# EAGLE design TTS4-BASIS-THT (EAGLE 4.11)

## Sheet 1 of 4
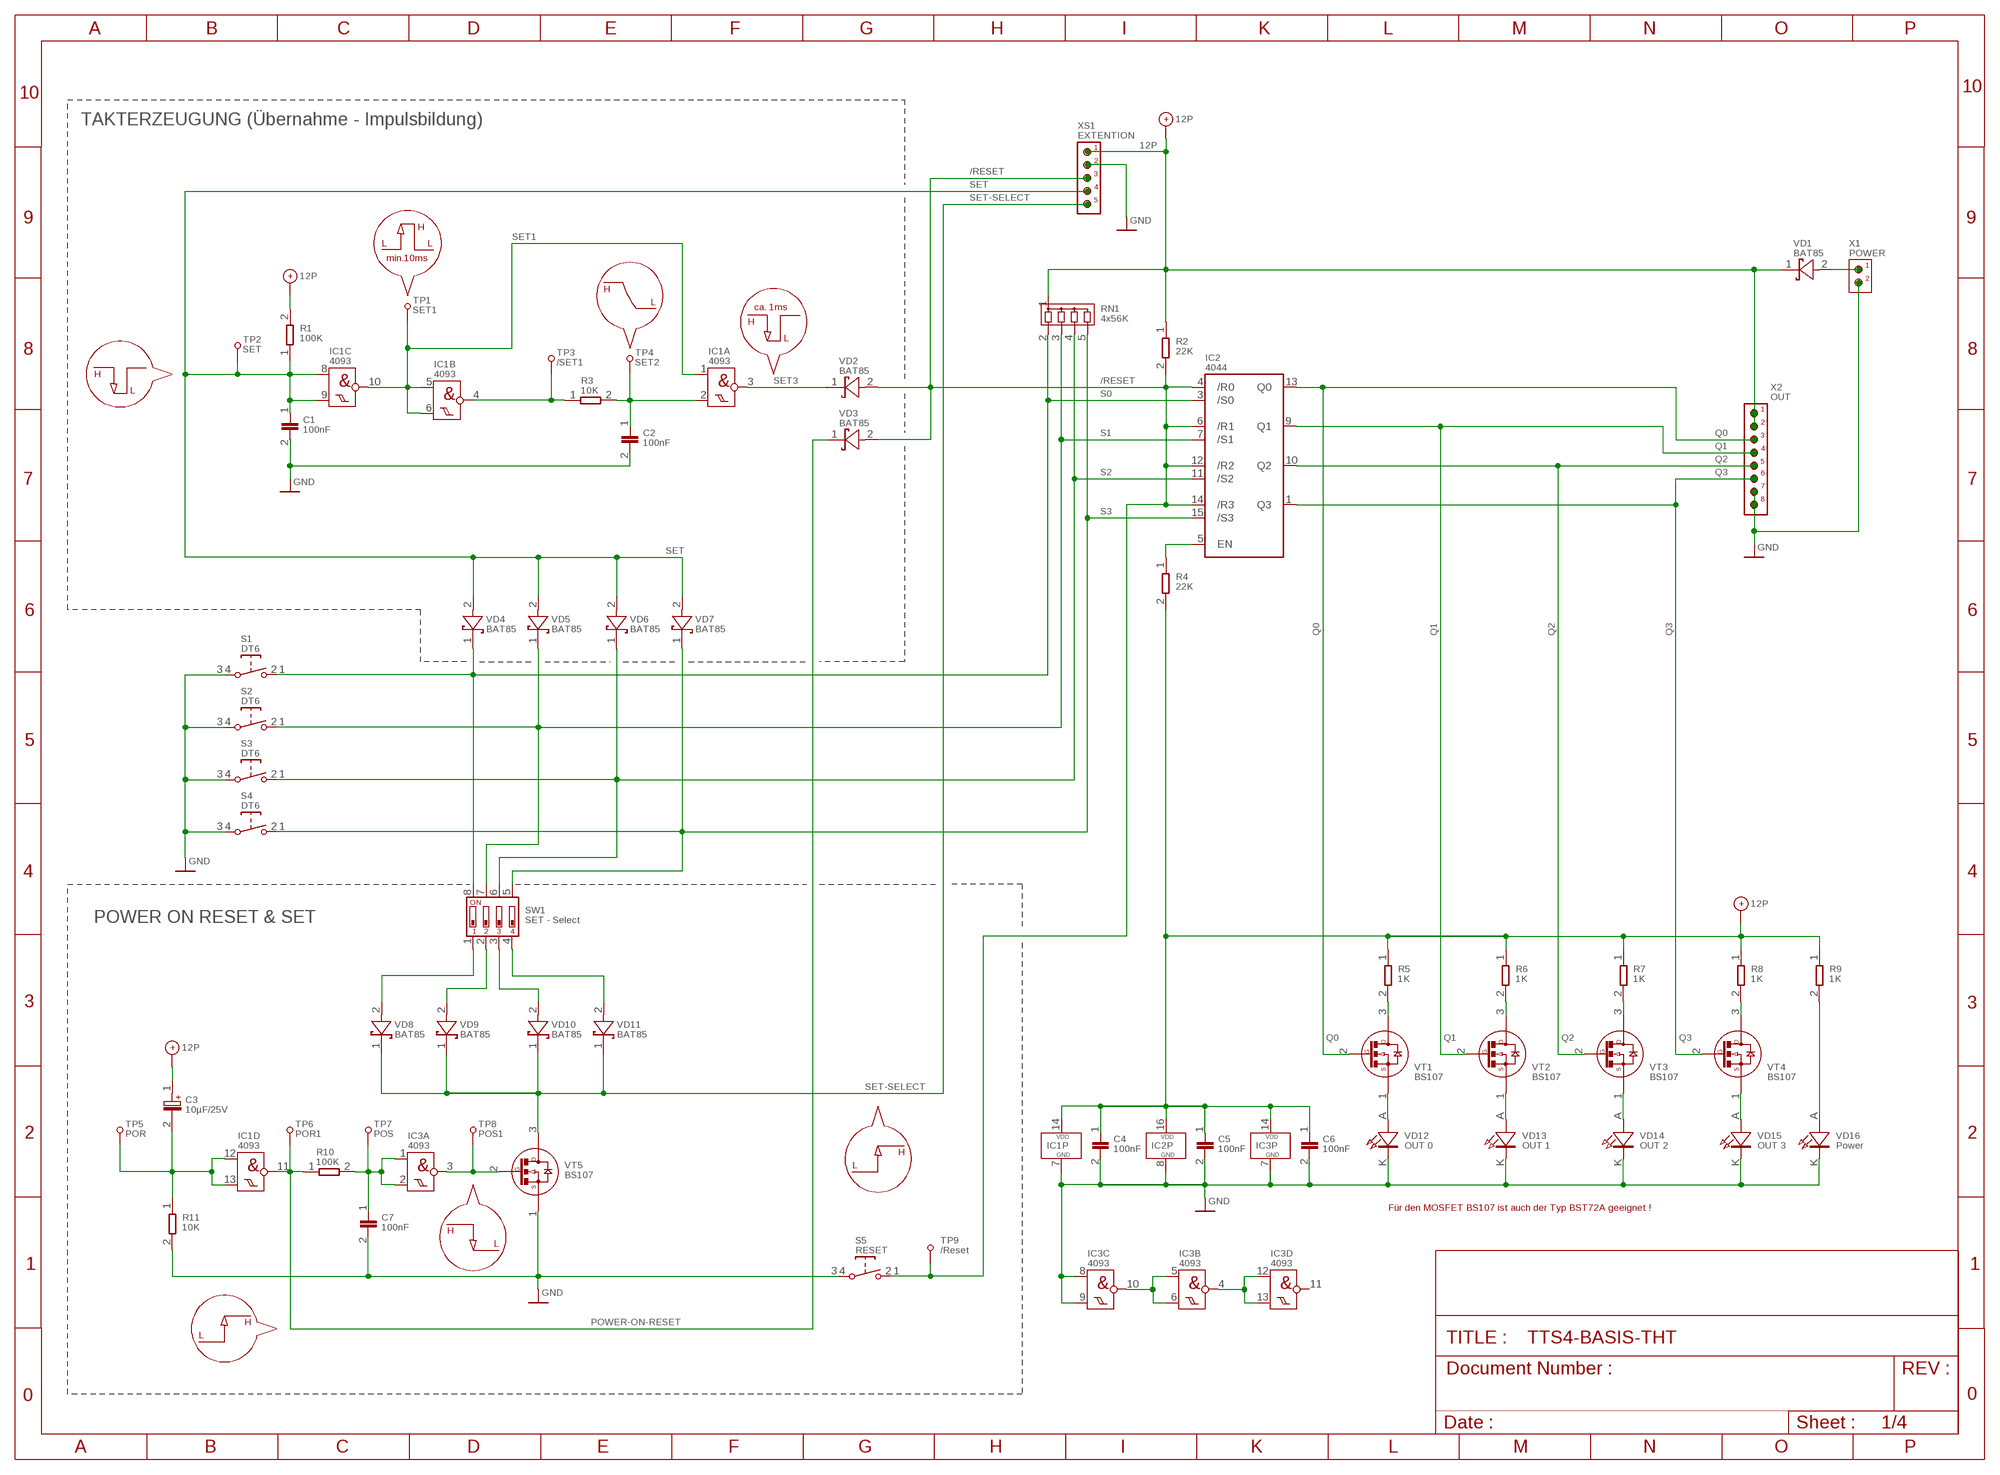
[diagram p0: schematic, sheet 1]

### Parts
C1  100nF  C-5  [C5]
C2  100nF  C-5  [C5]
C3  10µF/25V  ELKO_2,5-5  [EL2,5-5]
C4  100nF  C-5  [C5]
C5  100nF  C-5  [C5]
C6  100nF  C-5  [C5]
C7  100nF  C-5  [C5]
IC1  4093  4093_LP  [DIL14LP]
IC2  4044  4044_LP  [DIL16LP]
IC3  4093  4093_LP  [DIL14LP]
R1  100K  R0207-12,5  [R0207-12,5]
R2  22K  R0207-12,5  [R0207-12,5]
R3  10K  R0207-12,5  [R0207-12,5]
R4  22K  R0207-12,5  [R0207-12,5]
R5  1K  R0207-12,5  [R0207-12,5]
R6  1K  R0207-12,5  [R0207-12,5]
R7  1K  R0207-12,5  [R0207-12,5]
R8  1K  R0207-12,5  [R0207-12,5]
R9  1K  R0207-12,5  [R0207-12,5]
R10  100K  R0207-12,5  [R0207-12,5]
R11  10K  R0207-12,5  [R0207-12,5]
RN1  4x56K  RN4  [RN4]
S1  DT6  DT6-H  [DT6-HOLE]
S2  DT6  DT6-H  [DT6-HOLE]
S3  DT6  DT6-H  [DT6-HOLE]
S4  DT6  DT6-H  [DT6-HOLE]
S5  RESET  DT6-H  [DT6-HOLE]
SW1  SET - Select  SW_DIP-4EPG  [EDG-04]
TP1  SET1  TP1.5  [TP1.5MM]
TP2  SET  TP1.5  [TP1.5MM]
TP3  /SET1  TP1.5  [TP1.5MM]
TP4  SET2  TP1.5  [TP1.5MM]
TP5  POR  TP1.5  [TP1.5MM]
TP6  POR1  TP1.5  [TP1.5MM]
TP7  POS  TP1.5  [TP1.5MM]
TP8  POS1  TP1.5  [TP1.5MM]
TP9  /Reset  TP1.5  [TP1.5MM]
VD1  BAT85  BAT85-DO  [DO35-10]
VD2  BAT85  BAT85-DO  [DO35-10]
VD3  BAT85  BAT85-DO  [DO35-10]
VD4  BAT85  BAT85-DO  [DO35-10]
VD5  BAT85  BAT85-DO  [DO35-10]
VD6  BAT85  BAT85-DO  [DO35-10]
VD7  BAT85  BAT85-DO  [DO35-10]
VD8  BAT85  BAT85-DO  [DO35-10]
VD9  BAT85  BAT85-DO  [DO35-10]
VD10  BAT85  BAT85-DO  [DO35-10]
VD11  BAT85  BAT85-DO  [DO35-10]
VD12  OUT 0  LED3MM  [LED-3MM]
VD13  OUT 1  LED3MM  [LED-3MM]
VD14  OUT 2  LED3MM  [LED-3MM]
VD15  OUT 3  LED3MM  [LED-3MM]
VD16  Power  LED3MM  [LED-3MM]
VT1  BS107  BS107-92A  [TO92A0]
VT2  BS107  BS107-92A  [TO92A0]
VT3  BS107  BS107-92A  [TO92A0]
VT4  BS107  BS107-92A  [TO92A0]
VT5  BS107  BS107-92A  [TO92A0]
X1  POWER  PAD2_PF  [1X2]
X2  OUT  PAD8_PF  [1X8]
XS1  EXTENTION  PF1X5  [1X5]

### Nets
12P: C3.1 C4.1 C5.1 C6.1 IC1.14(P:VDD) IC2.16(VDD) IC3.14(P:VDD) R1.2 R2.1 R4.2 R5.1 R6.1 R7.1 R8.1 R9.1 RN1.1 VD1.1(K) X2.1 X2.2 XS1.1
12PIN: VD1.2(A) X1.1
/RESET: IC2.4(/R0) IC2.6(/R1) IC2.12(/R2) IC2.14(/R3) R2.2 S5.1(S) S5.2(S) TP9.1 VD2.2(A) VD3.2(A) XS1.3
/SET1: IC1.4(B:O) R3.1 TP3.1
GND: C1.2 C2.2 C4.2 C5.2 C6.2 C7.2 IC1.7(P:GND) IC2.8(GND) IC3.7(P:GND) IC3.8(C:I0) IC3.9(C:I1) R11.2 S1.3(P) S1.4(P) S2.3(P) S2.4(P) S3.3(P) S3.4(P) S4.3(P) S4.4(P) S5.3(P) S5.4(P) VD12.K VD13.K VD14.K VD15.K VD16.K VT5.1(S) X1.2 X2.7 X2.8 XS1.2
N$5: VD12.A VT1.1(S)
N$6: VD13.A VT2.1(S)
N$7: VD14.A VT3.1(S)
N$8: VD15.A VT4.1(S)
N$9: IC2.5(EN) R4.1
N$11: R5.2 VT1.3(D)
N$12: R6.2 VT2.3(D)
N$13: R7.2 VT3.3(D)
N$14: R8.2 VT4.3(D)
N$19: R9.2 VD16.A
N$20: IC3.5(B:I0) IC3.6(B:I1) IC3.10(C:O)
N$21: IC3.4(B:O) IC3.12(D:I0) IC3.13(D:I1)
POR: C3.2 IC1.12(D:I0) IC1.13(D:I1) R11.1 TP5.1
POS: C7.1 IC3.1(A:I0) IC3.2(A:I1) R10.2 TP7.1
POS1: IC3.3(A:O) TP8.1 VT5.2(G)
POWER-ON-RESET: IC1.11(D:O) R10.1 TP6.1 VD3.1(K)
Q0: IC2.13(Q0) VT1.2(G) X2.3
Q1: IC2.9(Q1) VT2.2(G) X2.4
Q2: IC2.10(Q2) VT3.2(G) X2.5
Q3: IC2.1(Q3) VT4.2(G) X2.6
S0: IC2.3(/S0) RN1.2 S1.1(S) S1.2(S) SW1.8 VD4.1(K)
S1: IC2.7(/S1) RN1.3 S2.1(S) S2.2(S) SW1.7 VD5.1(K)
S2: IC2.11(/S2) RN1.4 S3.1(S) S3.2(S) SW1.6 VD6.1(K)
S3: IC2.15(/S3) RN1.5 S4.1(S) S4.2(S) SW1.5 VD7.1(K)
SET: C1.1 IC1.8(C:I0) IC1.9(C:I1) R1.1 TP2.1 VD4.2(A) VD5.2(A) VD6.2(A) VD7.2(A) XS1.4
SET1: IC1.1(A:I0) IC1.5(B:I0) IC1.6(B:I1) IC1.10(C:O) TP1.1
SET2: C2.1 IC1.2(A:I1) R3.2 TP4.1
SET3: IC1.3(A:O) VD2.1(K)
SET-SELECT: VD8.1(K) VD9.1(K) VD10.1(K) VD11.1(K) VT5.3(D) XS1.5
SL1: SW1.1 VD8.2(A)
SL2: SW1.2 VD9.2(A)
SL3: SW1.3 VD10.2(A)
SL4: SW1.4 VD11.2(A)
Unconnected: IC3.11(D:O)

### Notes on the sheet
- TAKTERZEUGUNG (Übernahme - Impulsbildung)
- H
- L | L
- min.10ms
- H
- L
- ca. 1ms
- H
- L
- H
- L
- POWER ON RESET & SET
- H
- L
- Für den MOSFET BS107 ist auch der Typ BST72A geeignet !
- H
- L
- H
- L

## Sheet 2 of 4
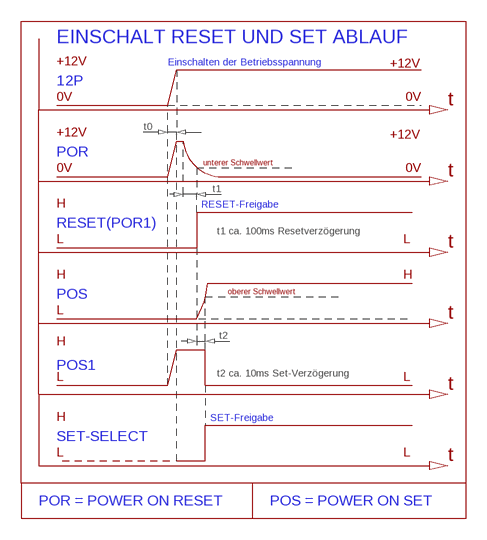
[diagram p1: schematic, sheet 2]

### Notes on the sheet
- EINSCHALT RESET UND SET ABLAUF
- +12V | Einschalten der Betriebsspannung | +12V
- 12P
- 0V | 0V
- t
- t0
- +12V | +12V
- POR
- unterer Schwellwert
- 0V | 0V
- t
- t1
- H | RESET-Freigabe
- RESET(POR1)
- t1 ca. 100ms Resetverzögerung
- L | L
- t
- H | H
- oberer Schwellwert
- POS
- L
- t
- t2
- H
- POS1
- t2 ca. 10ms Set-Verzögerung
- L | L
- t
- H | SET-Freigabe
- SET-SELECT
- L | L
- t
- POR = POWER ON RESET | POS = POWER ON SET

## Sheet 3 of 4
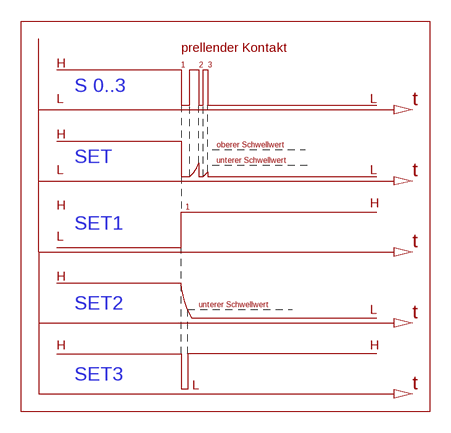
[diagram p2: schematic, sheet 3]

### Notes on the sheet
- prellender Kontakt
- H | 1 | 2 | 3
- S 0..3
- L | L | t
- H
- oberer Schwellwert
- SET | unterer Schwellwert
- L | L | t
- H | 1 | H
- SET1
- L
- t
- H
- SET2 | unterer Schwellwert
- L
- t
- H | H
- SET3
- L | t

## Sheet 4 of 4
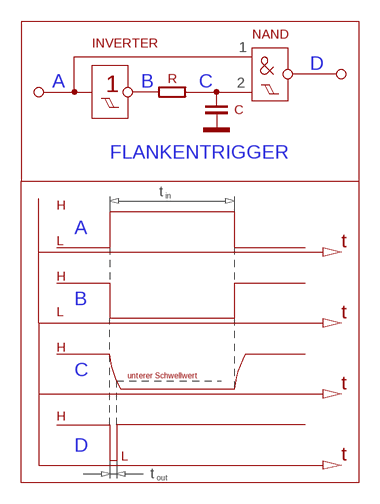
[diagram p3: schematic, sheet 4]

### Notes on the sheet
- NAND
- INVERTER
- 1
- D
- R
- A | 1 | B | C | 2
- C
- FLANKENTRIGGER
- t | in
- H
- A
- L | t
- H
- B
- L | t
- H
- C | unterer Schwellwert
- t
- H
- D
- L | t
- t | out

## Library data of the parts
C1 C2 C4-C7 = RLC:C-: Kondensator
C3 = RLC:ELKO_: ELKO
IC1 IC3 = 40XX:4093_: vier NAND Gatter mit je zwei Schmitt - Trigger - Eingängen
IC2 = 40XX:4044_: vier RS - Flip - Flop mit Tristate - Ausgängen
R1-R11 = RLC:R: Widerstand
RN1 = RLC:RN4: Widerstandsnetzwerk mit 4 Widerständen , einseitig zusammengeschaltet
S1-S5 = SWITCH:DT: ITT SWITCH
SW1 = DIL - SW:SW_DIP-4
TP1-TP9 = CON1:TP: Testpunkt mit 2 mm Durchmesser
VD1-VD11 = DIODEN:BAT85-: Kleinsignal Schottkydiode
VD12-VD16 = OPTO:LED
VT1-VT5 = TRANS:BS107-: N - Channel Enhancement TMOS - Transistor
X1 = PAD:PAD2_: 2 Lötpads
X2 = PAD:PAD8_: 8 Lötpads
XS1 = PF:PF1X5

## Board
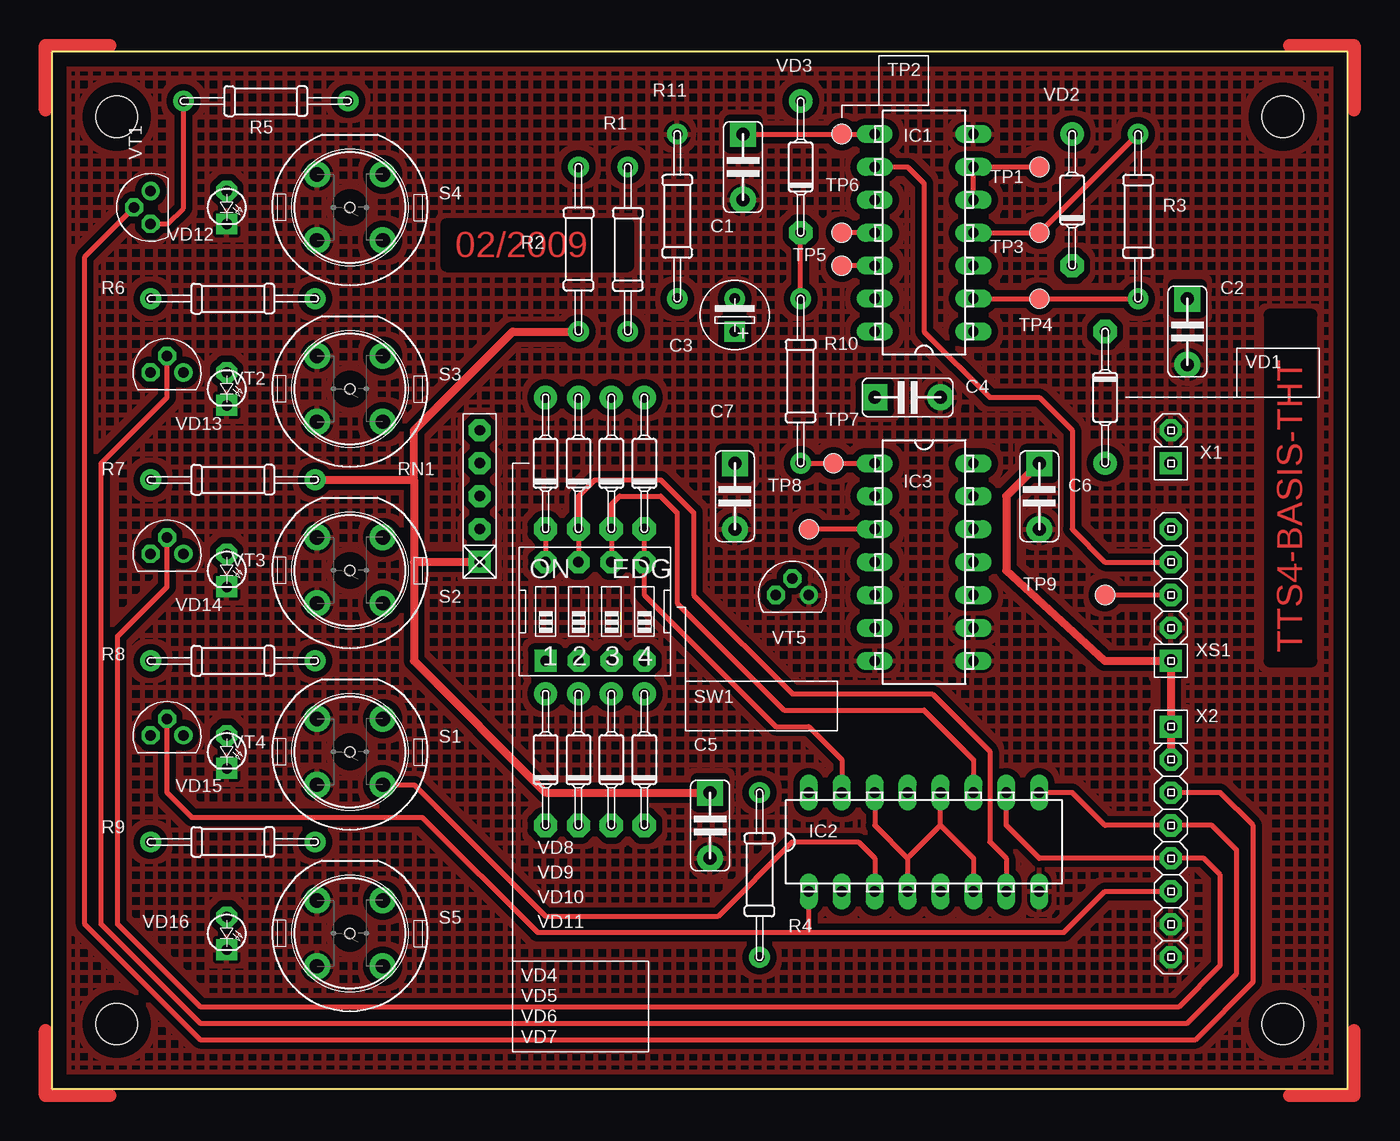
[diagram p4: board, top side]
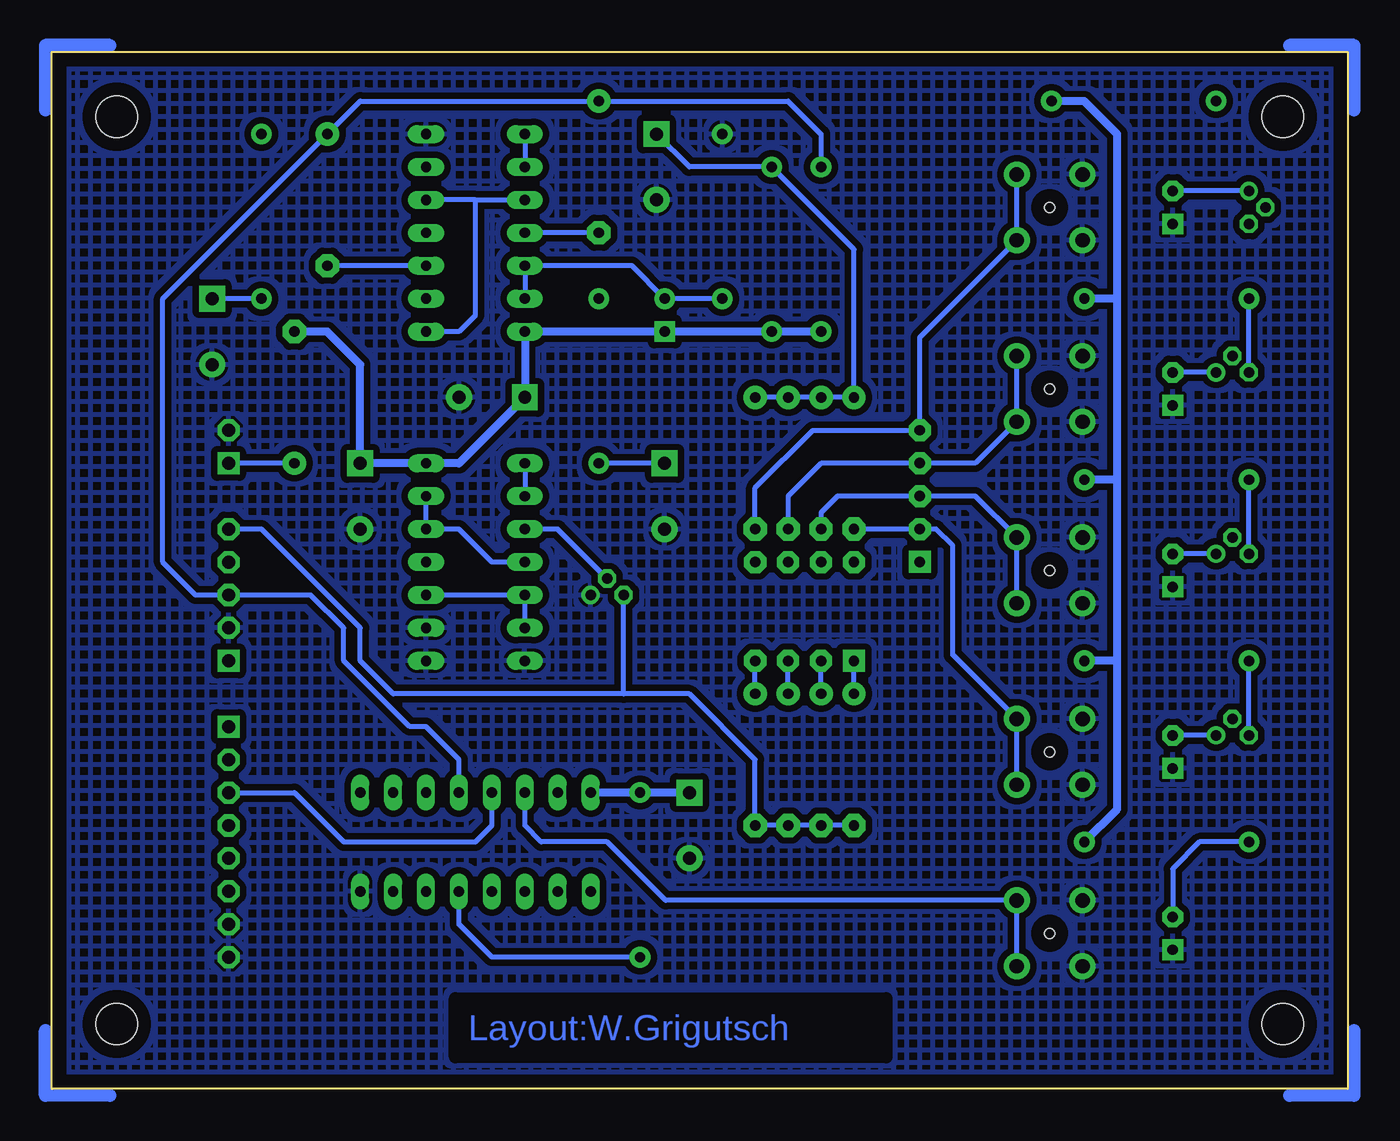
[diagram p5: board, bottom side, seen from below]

Size 100 x 80 mm. Coordinates in mm from the lower left corner, seen from the top.
Outline: 0,0 100,0 100,80 0,80 0,0
Copper layers (1*16): Top 0.035mm / dielectric 1.5mm / Bottom 0.035mm
Design rules "default": minimum track width 10mil, minimum drill 20mil, track to track 8mil, track to pad 8mil, pad to pad 8mil, via to via 8mil, smd to smd 8mil, copper to edge 40mil, drill to drill 8mil, minimum pad ring 10mil, minimum via ring 8mil, stop-mask expansion 4mil, vias tented up to drill 0mil, thermal gap 10mil
Holes 3.2 mm at 5,5 95,5 5,75 95,75
tRestrict: area 94,33 to 97.2,59.7; area 30.5,63.5 to 44.5,66.7
bRestrict: area 35.6,2.5 to 68.9,7

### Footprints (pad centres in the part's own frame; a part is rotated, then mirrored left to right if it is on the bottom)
C5 = drill 1 pad 2 square: 1 -2.54,0 | drill 1 pad 2 round: 2 2.54,0
EL2,5-5 = drill 0.8 pad 1.6 square: 1 -1.27,0 | drill 0.8 pad 1.6 round: 2 1.27,0
DIL14LP = drill 0.8 pad 1.4 long: 1 -6.985,-3.81; 2 -4.445,-3.81; 3 -1.905,-3.81; 4 0.635,-3.81; 5 3.175,-3.81; 6 5.715,-3.81; 7 8.255,-3.81; 8 8.255,3.81; 9 5.715,3.81; 10 3.175,3.81; 11 0.635,3.81; 12 -1.905,3.81; 13 -4.445,3.81; 14 -6.985,3.81
DIL16LP = drill 0.8 pad 1.4 long: 1 -8.89,-3.81; 2 -6.35,-3.81; 3 -3.81,-3.81; 4 -1.27,-3.81; 5 1.27,-3.81; 6 3.81,-3.81; 7 6.35,-3.81; 8 8.89,-3.81; 9 8.89,3.81; 10 6.35,3.81; 11 3.81,3.81; 12 1.27,3.81; 13 -1.27,3.81; 14 -3.81,3.81; 15 -6.35,3.81; 16 -8.89,3.81
R0207-12,5 = drill 0.8 pad 1.6 round: 1 -6.35,0; 2 6.35,0
RN4 = drill 0.8 pad 1.7 square: 1 -5.08,0 | drill 0.8 pad 1.7 octagon: 2 -2.54,0; 3 0,0; 4 2.54,0; 5 5.08,0
DT6-HOLE = drill 1.1 pad 2 round: 1 -2.54,2.54; 2 2.54,2.54; 3 2.54,-2.54; 4 -2.54,-2.54 | hole 0.8: 0,0
EDG-04 = drill 0.8 pad 1.7 square: 1 -3.81,-3.81 | drill 0.8 pad 1.7 octagon: 2 -1.27,-3.81; 3 1.27,-3.81; 4 3.81,-3.81; 5 3.81,3.81; 6 1.27,3.81; 7 -1.27,3.81; 8 -3.81,3.81
TP1.5MM = smd 1.5 x 1.5: 1 0,0
DO35-10 = drill 0.8 pad 1.8 octagon: 1 -5.08,0 | drill 0.8 pad 1.8 round: 2 5.08,0
LED-3MM = drill 0.8 pad 1.6 octagon: A 1.27,0 | drill 0.8 pad 1.6 square: K -1.27,0
TO92A0 = drill 0.813 pad 1.4 round: 1 1.27,0 | drill 0.813 pad 1.4 octagon: 2 0,1.27; 3 -1.27,0
1X2 = drill 1 pad 1.7 square: 1 -1.27,0 | drill 1 pad 1.7 octagon: 2 1.27,0
1X8 = drill 1 pad 1.7 square: 1 -8.89,0 | drill 1 pad 1.7 octagon: 2 -6.35,0; 3 -3.81,0; 4 -1.27,0; 5 1.27,0; 6 3.81,0; 7 6.35,0; 8 8.89,0
1X5 = drill 1 pad 1.7 square: 1 -5.08,0 | drill 1 pad 1.7 octagon: 2 -2.54,0; 3 0,0; 4 2.54,0; 5 5.08,0

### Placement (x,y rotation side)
C1  53.34,71.12 270 top
C2  87.63,58.42 270 top
C3  52.7,59.69 90 top
C4  66.04,53.34 0 top
C5  50.8,20.32 270 top
C6  76.2,45.72 270 top
C7  52.7,45.72 270 top
IC1  67.31,65.41 90 top
IC2  67.31,19.05 0 top
IC3  67.31,41.27 270 top
R1  44.45,64.77 270 top
R2  40.64,64.77 90 top
R3  83.82,67.31 270 top
R4  54.61,16.51 90 top
R5  16.51,76.2 180 top
R6  13.97,60.96 180 top
R7  13.97,46.99 180 top
R8  13.97,33.02 180 top
R9  13.97,19.05 180 top
R10  57.78,54.61 270 top
R11  48.26,67.31 90 top
RN1  33.02,45.73 90 top
S1  23,26 270 top
S2  23,40 270 top
S3  23,54 270 top
S4  23,68 270 top
S5  23,12 270 top
SW1  41.91,36.83 0 top
TP1  76.2,71.12 270 top
TP2  60.96,73.66 90 top
TP3  76.2,66.04 0 top
TP4  76.2,60.96 180 top
TP5  60.96,63.5 180 top
TP6  60.96,66.04 90 top
TP7  60.33,48.26 180 top
TP8  58.42,43.18 270 top
TP9  81.28,38.1 90 top
VD1  81.28,53.34 270 top
VD2  78.74,68.58 90 top
VD3  57.78,71.12 90 top
VD4  38.1,48.26 90 top
VD5  40.64,48.26 90 top
VD6  43.18,48.26 90 top
VD7  45.72,48.26 90 top
VD8  38.1,25.4 90 top
VD9  40.64,25.4 90 top
VD10  43.18,25.4 90 top
VD11  45.72,25.4 90 top
VD12  13.5,68 90 top
VD13  13.5,54 90 top
VD14  13.5,40 90 top
VD15  13.5,26 90 top
VD16  13.5,12 90 top
VT1  7.62,68 90 top
VT2  8.89,55.27 0 top
VT3  8.89,41.27 0 top
VT4  8.89,27.27 0 top
VT5  57.15,38.1 0 top
X1  86.36,49.53 90 top
X2  86.36,19.05 270 top
XS1  86.36,38.1 90 top

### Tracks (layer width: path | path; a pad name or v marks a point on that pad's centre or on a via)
12P
  Top 0.4: RN1.1 27.94,40.64 27.94,40.65
  Top 0.6: R7.1 27.94,46.99 | 27.94,46.99 27.94,40.64 27.94,33.02 38.1,22.86 C5.1 | X2.2 X2.1 XS1.1 81.28,33.02 73.66,40.01 73.66,45.72 C6.1 | 27.94,40.65 RN1.1 | R2.1 35.56,58.42 27.94,50.8 27.94,46.99
  Bottom 0.6: R9.1 17.78,21.59 17.78,33.02 | 17.78,33.02 R8.1 | 17.78,33.02 17.78,46.99 | 17.78,46.99 R7.1 | 17.78,46.99 17.78,60.96 | 17.78,60.96 R6.1 | 17.78,60.96 17.78,73.66 20.32,76.2 R5.1 | R2.1 R1.2 C3.1 IC1.14 C4.1 68.58,48.26 IC3.14 C6.1 76.2,55.88 78.74,58.42 VD1.1 | IC2.16 R4.2 C5.1
12PIN
  Bottom 0.4: VD1.2 X1.1
/RESET
  Top 0.4: 66.04,17.78 IC2.4 | 66.04,17.78 63.5,20.32 IC2.14 | 68.58,20.32 IC2.12 | 66.04,17.78 68.58,20.32 | IC2.6 71.12,17.78 68.58,20.32 | XS1.3 TP9.1
  Bottom 0.4: R2.2 40.64,73.66 43.18,76.2 VD3.2 76.2,76.2 | S5.2 S5.1 52.64,14.54 57.15,19.05 62.23,19.05 63.5,20.32 IC2.14 | IC2.12 68.58,25.4 71.12,27.94 72.39,27.94 77.47,33.02 77.47,35.56 80.01,38.1 XS1.3 88.9,38.1 91.44,40.64 91.44,60.96 76.2,76.2 | 76.2,76.2 VD2.2
/SET1
  Top 0.4: IC1.4 TP3.1 R3.1
GND
  pour Bottom (isolate 0.5, hatched): 1,1 1,79 99,79 99,1
  pour Top (isolate 0.5, hatched): 1,79 1,1 99,1 99,79
N$2
  Top 1: 4.5,-0.5 -0.5,-0.5 -0.5,4.5
N$3
  Top 1: 95.5,-0.5 100.5,-0.5 100.5,4.5
N$4
  Top 1: 4.5,80.5 -0.5,80.5 -0.5,75.5
N$5
  Bottom 0.4: VT1.1 VD12.A
N$6
  Bottom 0.4: VT2.1 VD13.A
N$7
  Bottom 0.4: VT3.1 VD14.A
N$8
  Bottom 0.4: VT4.1 VD15.A
N$9
  Bottom 0.4: R4.1 66.04,10.16 68.58,12.7 IC2.5
N$10
  Top 1: 100.5,75.5 100.5,80.5 95.5,80.5
N$11
  Top 0.4: VT1.3 8.95,66.73 10.16,67.94 R5.2
N$12
  Bottom 0.4: VT2.3 R6.2
N$13
  Bottom 0.4: VT3.3 R7.2
N$14
  Bottom 0.4: VT4.3 R8.2
N$15
  Bottom 1: 4.5,-0.5 -0.5,-0.5 -0.5,4.5
N$16
  Bottom 1: 95.5,-0.5 100.5,-0.5 100.5,4.5
N$17
  Bottom 1: 4.5,80.5 -0.5,80.5 -0.5,75.5
N$18
  Bottom 1: 100.5,75.5 100.5,80.5 95.5,80.5
N$19
  Bottom 0.4: R9.2 11.43,19.05 13.5,16.98 VD16.A
N$20
  Bottom 0.4: IC3.6 IC3.5 IC3.10
N$21
  Bottom 0.4: IC3.4 66.04,40.64 68.58,43.18 IC3.12 IC3.13
POR
  Top 0.4: IC1.12 TP5.1
  Bottom 0.4: IC1.13 IC1.12 55.24,63.5 C3.2 R11.1
POS
  Top 0.4: IC3.1 TP7.1 R10.2
  Bottom 0.4: IC3.1 IC3.2 | C7.1 R10.2
POS1
  Top 0.4: IC3.3 TP8.1
  Bottom 0.4: VT5.2 60.96,43.18 IC3.3
POWER-ON-RESET
  Top 0.4: R10.1 VD3.1 | IC1.11 TP6.1
  Bottom 0.4: VD3.1 IC1.11
Q0
  Top 0.4: X2.3 90.17,22.86 92.71,20.32 92.71,8.26 88.27,3.81 11.43,3.81 2.54,12.7 2.54,64.19 VT1.2
  Bottom 0.4: X2.3 81.28,22.86 77.47,19.05 67.31,19.05 66.04,20.32 IC2.13
Q1
  Top 0.4: IC2.9 78.74,22.86 81.28,20.32 X2.4 89.53,20.32 91.44,18.41 91.44,8.89 87.63,5.08 11.43,5.08 3.81,12.7 3.81,48.26 8.89,53.34 VT2.2
Q2
  Top 0.4: IC2.10 73.66,20.32 76.2,17.78 X2.5 88.9,17.78 90.17,16.51 90.17,9.53 87,6.35 11.43,6.35 5.08,12.7 5.08,34.92 8.89,38.73 VT3.2
Q3
  Top 0.4: X2.6 81.28,15.24 78.11,12.06 58.42,12.06 | 58.42,12.06 IC2.1 | 58.42,12.06 37.47,12.06 28.57,20.95 10.79,20.95 8.89,22.86 VT4.2
S0
  Top 0.4: IC2.3 63.5,17.78 62.23,19.05 57.15,19.05 51.44,13.34 38.1,13.34 27.98,23.46 S1.2 | VD4.1 SW1.8
  Bottom 0.4: VD4.1 RN1.2 31.76,43.19 30.48,41.91 30.48,33.48 S1.1 S1.2
S1
  Top 0.4: IC2.7 73.66,17.78 72.39,19.05 72.39,26.04 67.94,30.48 57.15,30.48 49.53,38.1 49.53,44.45 46.99,46.99 41.91,46.99 40.64,45.72 VD5.1 SW1.7
  Bottom 0.4: VD5.1 40.64,44.45 39.37,45.72 RN1.3 28.73,45.73 S2.1 S2.2
S2
  Top 0.4: IC2.11 71.12,25.4 67.31,29.21 56.52,29.21 48.26,37.47 48.26,44.45 46.99,45.72 43.81,45.72 43.18,45.09 VD6.1 SW1.6
  Bottom 0.4: VD6.1 43.18,45.72 40.64,48.26 RN1.4 28.73,48.27 S3.2 S3.1
S3
  Top 0.4: IC2.15 60.96,25.4 58.42,27.94 55.88,27.94 45.73,38.09 SW1.5 VD7.1
  Bottom 0.4: VD7.1 45.72,46.35 41.27,50.8 RN1.5 33.02,57.98 S4.2 S4.1
SET
  Top 0.4: IC1.8 TP2.1 C1.1 | XS1.4 81.28,40.64 78.74,43.18 78.74,50.8 76.2,53.34 72.39,53.34 67.31,58.42 67.31,69.85 66.04,71.12 IC1.9
  Bottom 0.4: IC1.8 IC1.9 | VD7.2 VD6.2 VD5.2 VD4.2 38.1,64.77 R1.1 50.8,71.12 C1.1
SET1
  Top 0.4: TP1.1 IC1.6 IC1.5
  Bottom 0.4: 67.31,68.58 IC1.10 | 67.31,68.58 IC1.5 | IC1.1 68.58,58.42 67.31,59.69 67.31,68.58
SET2
  Top 0.4: IC1.2 TP4.1 R3.2
  Bottom 0.4: R3.2 C2.1
SET3
  Bottom 0.4: IC1.3 VD2.1
SET-SELECT
  Bottom 0.4: VD8.1 VD9.1 VD10.1 VD11.1 45.72,25.4 50.8,30.48 55.88,30.48 | 55.88,30.48 VT5.3 | XS1.5 83.82,43.18 76.2,35.56 76.2,33.02 73.66,30.48 55.88,30.48
SL1
  Bottom 0.4: VD8.2 SW1.1
SL2
  Bottom 0.4: VD9.2 SW1.2
SL3
  Bottom 0.4: VD10.2 SW1.3
SL4
  Bottom 0.4: VD11.2 SW1.4

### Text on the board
Top: 02/2009 | TTS4-BASIS-THT
Bottom: Layout:W.Grigutsch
